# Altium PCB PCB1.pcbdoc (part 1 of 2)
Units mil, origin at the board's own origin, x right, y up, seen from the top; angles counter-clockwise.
Board outline 1771.65 x 1825.33 mil, 2 copper layers (Top Layer, Bottom Layer), stack 62.206 mil thick; 72 components, 46 nets, 229 pads, 305 vias.
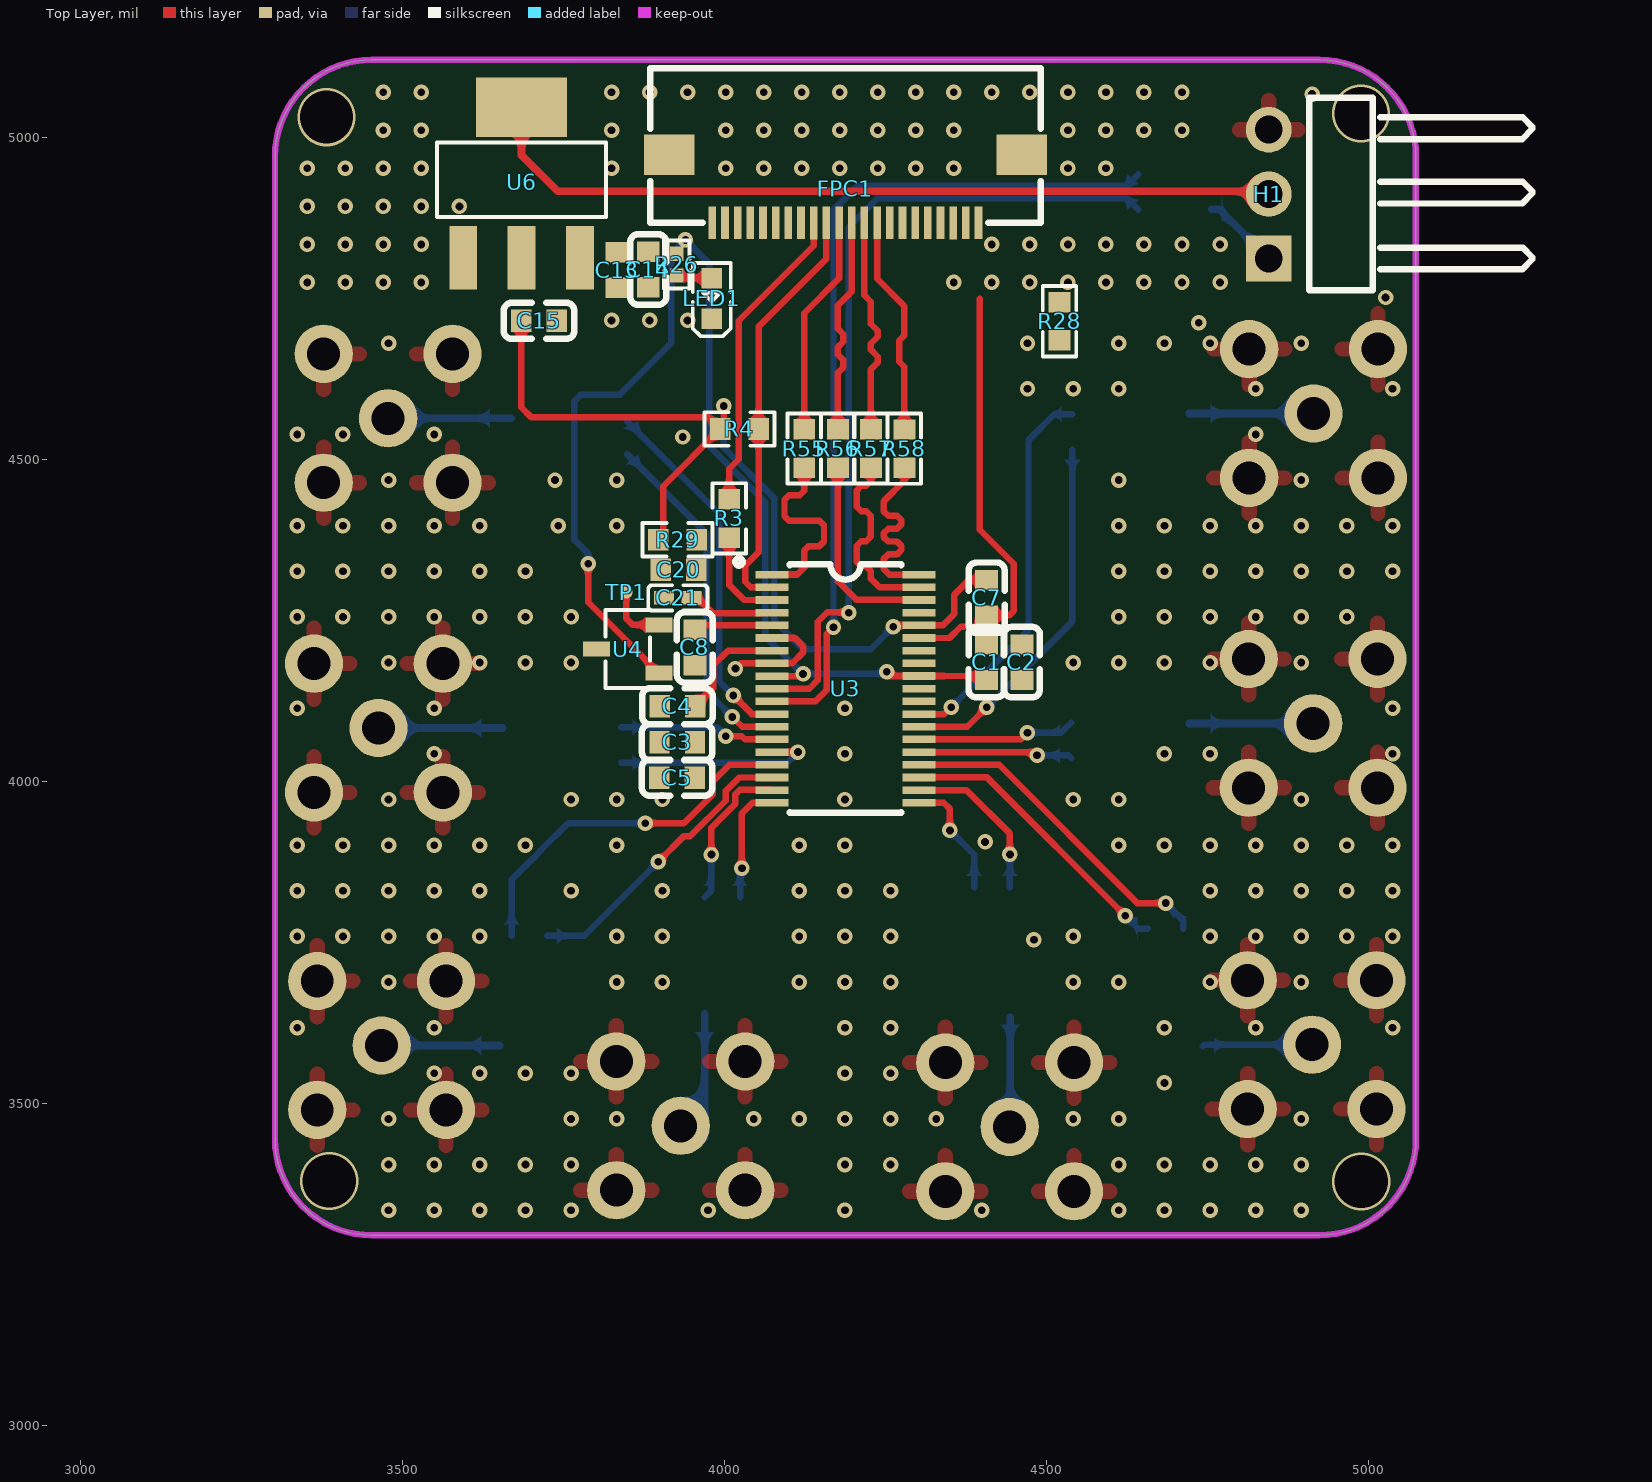
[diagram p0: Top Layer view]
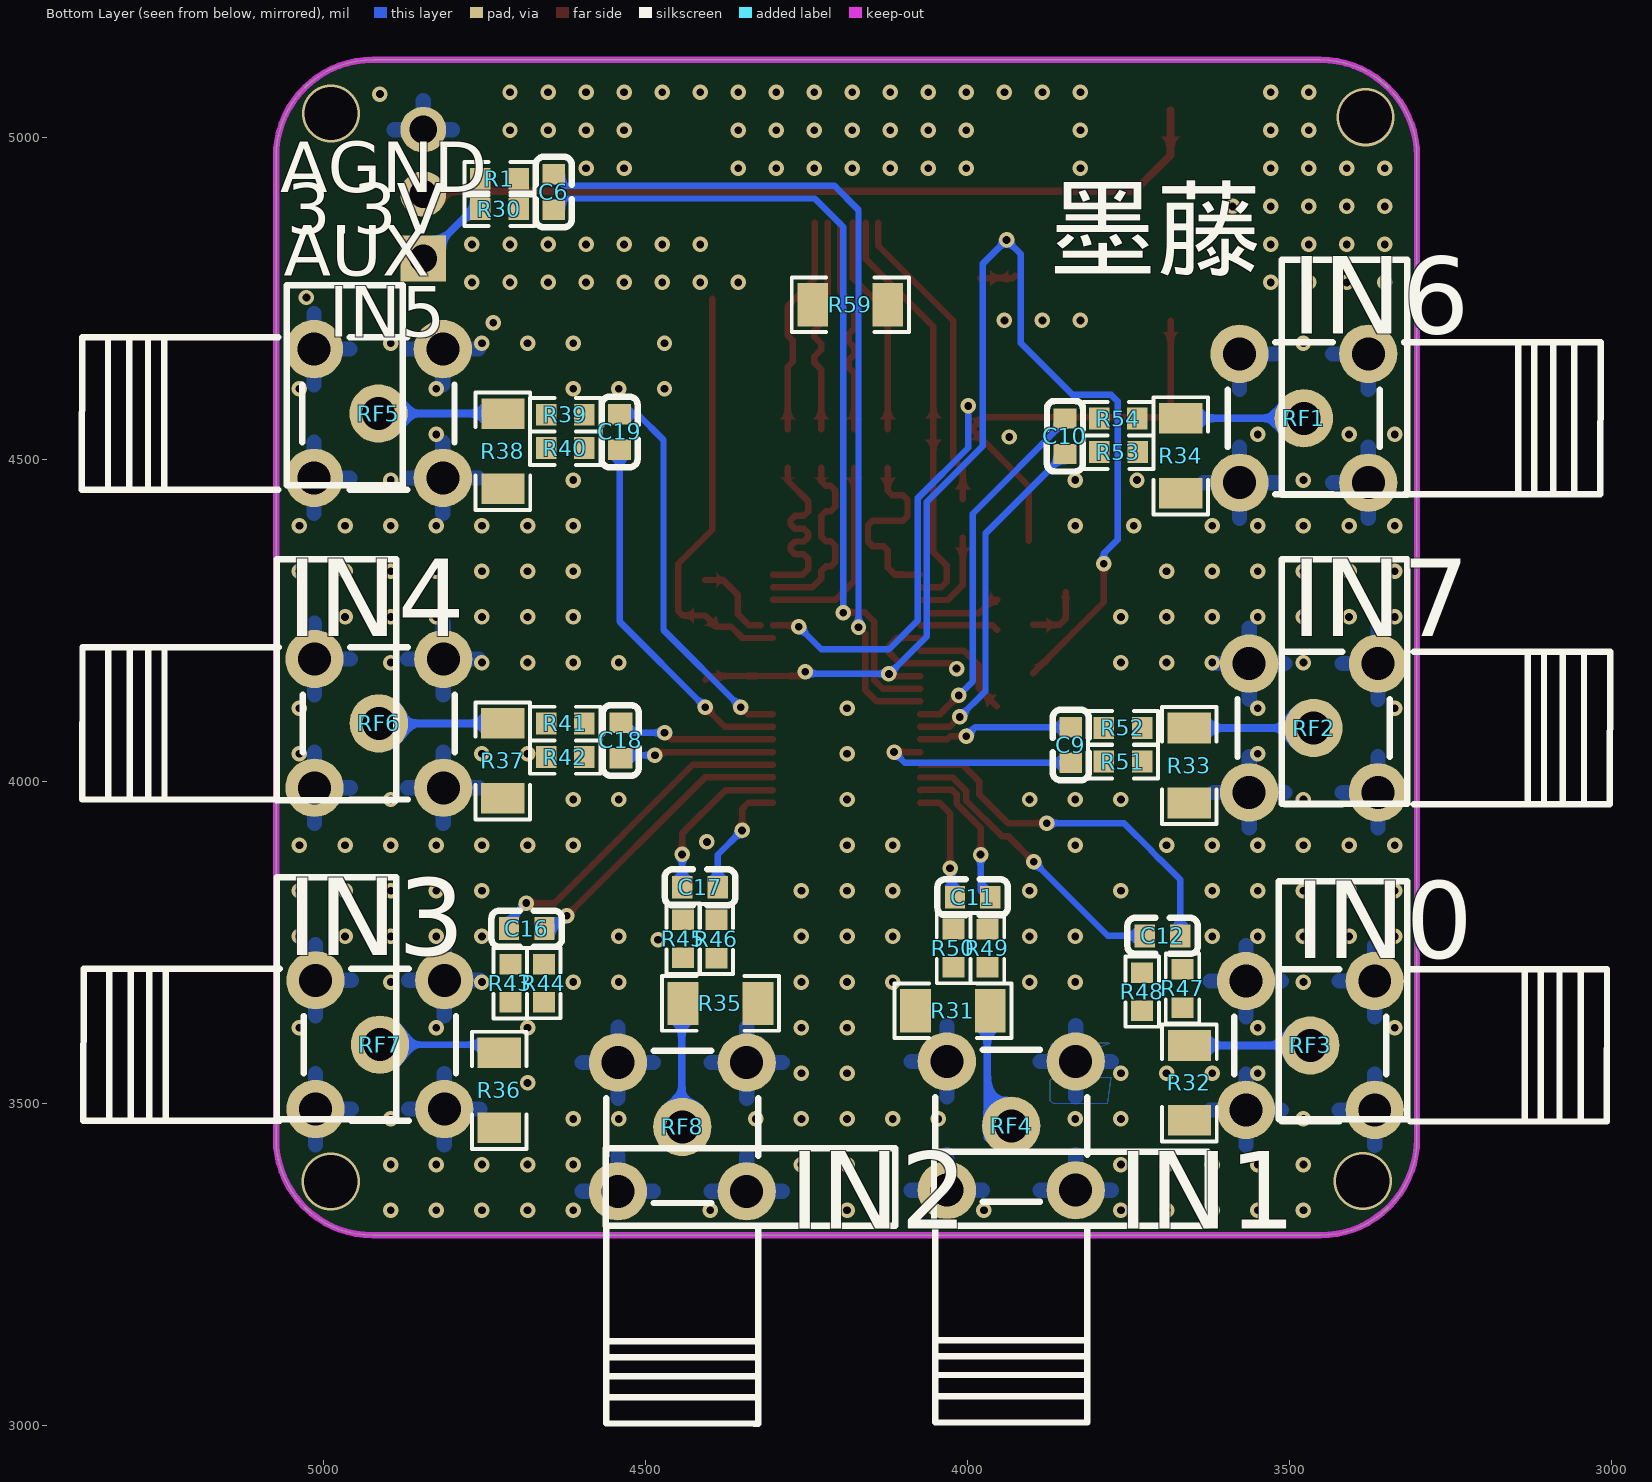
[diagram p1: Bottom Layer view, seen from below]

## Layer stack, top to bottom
Top Solder Mask Layer: solder mask 0.394, Dk 3.3
Top Layer: signal copper 1.379
Dielectric1: surface 59.449, FR4, Dk 4.5
Bottom Layer: signal copper 1.378
Bottom Solder Mask Layer: solder mask 0.394, Dk 3.3

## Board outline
3452.36,3294.69 4924.01,3294.69 ccw(c4924.01,3444.69) 5074.01,3444.69 5074.01,4970.05 ccw(c4924.03,4970.04) 4924.01,5120.02 3452.36,5120.02 ccw(c3452.34,4970.04) 3302.36,4970.05 3302.36,3444.69 ccw(c3452.36,3444.69)

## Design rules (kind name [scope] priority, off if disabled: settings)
BoardOutlineClearance copperThickness1oz [All] p0: genericclearance=10 ignorepadtopadclearanceinfootprint=FALSE except(0: Arc-SplitContinuation Track-SplitContinuation SMDPad-SplitContinuation THPad-SplitContinuation Via-SplitContinuation Fill-SplitContinuation Poly-SplitContinuation Region-SplitContinuation Text-SplitContinuation)
BoardOutlineClearance copperThickness2oz [All] p0: genericclearance=10 ignorepadtopadclearanceinfootprint=FALSE except(0: Arc-SplitContinuation Track-SplitContinuation SMDPad-SplitContinuation THPad-SplitContinuation Via-SplitContinuation Fill-SplitContinuation Poly-SplitContinuation Region-SplitContinuation Text-SplitContinuation)
BoardOutlineClearance Plane_innerPlane [All] p0: genericclearance=10 ignorepadtopadclearanceinfootprint=FALSE except(0: Arc-SplitContinuation Track-SplitContinuation SMDPad-SplitContinuation THPad-SplitContinuation Via-SplitContinuation Fill-SplitContinuation Poly-SplitContinuation Region-SplitContinuation Text-SplitContinuation)
BoardOutlineClearance Copper_copperRegion [All] p0: genericclearance=10 ignorepadtopadclearanceinfootprint=FALSE except(0: Arc-SplitContinuation Track-SplitContinuation SMDPad-SplitContinuation THPad-SplitContinuation Via-SplitContinuation Fill-SplitContinuation Poly-SplitContinuation Region-SplitContinuation Text-SplitContinuation)
BoardOutlineClearance otherClearance [All] p0: genericclearance=10 ignorepadtopadclearanceinfootprint=FALSE except(0: Arc-SplitContinuation Track-SplitContinuation SMDPad-SplitContinuation THPad-SplitContinuation Via-SplitContinuation Fill-SplitContinuation Poly-SplitContinuation Region-SplitContinuation Text-SplitContinuation)
Clearance copperThickness1oz [All] p1: gap=7 ignorepadtopadclearanceinfootprint=FALSE
Clearance copperThickness2oz [All] p1: gap=7 ignorepadtopadclearanceinfootprint=FALSE
Clearance Plane_innerPlane [All] p1: gap=7 ignorepadtopadclearanceinfootprint=FALSE
Clearance Copper_copperRegion [All] p1: gap=7 ignorepadtopadclearanceinfootprint=FALSE
Clearance otherClearance [All] p1: gap=7 ignorepadtopadclearanceinfootprint=FALSE
DiffPairsRouting differentialPair [All] p1: maxuncoupledlength=10 minlimit=6 maxlimit=Infinity mostfreqgap=6 toplayer_minwidth=5 toplayer_prefwidth=10 toplayer_maxwidth=100 bottomlayer_minwidth=5 bottomlayer_prefwidth=10 bottomlayer_maxwidth=100
PasteMaskExpansion pasteMaskExpansion [All] p1: expansion=0
PlaneConnect innerPlane [All] p1: planeconnectstyle=Relief reliefexpansion=20 reliefentries=4 reliefconductorwidth=10 reliefairgap=10
PolygonConnect copperRegion [All] p1: connectstyle=Relief reliefentries=4 reliefconductorwidth=23.622 polygonreliefangle="90 Angle" airgapwidth=10
RoutingVias viaSize [All] p1: viastyle="Through Hole" holewidth=12.0078 minholewidth=11.811 maxholewidth=248.0314 width=12.0078 minwidth=11.811 maxwidth=248.0314
SolderMaskExpansion solderMaskExpansion [All] p1: useseparateexpansions=TRUE expansion=2 expansionbottom=2
Width copperThickness1oz [All] p1: maxlimit=100 minlimit=5 preferedwidth=10
Width copperThickness2oz [All] p1: maxlimit=100 minlimit=8 preferedwidth=10

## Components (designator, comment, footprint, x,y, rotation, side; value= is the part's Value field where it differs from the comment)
C1 "" C0603 4407.22,4184.71 r90 top
C2 "" C0603 4462.22,4184.71 r90 top
C3 "" C0603 3926.83,4060.33 r0 top
C4 "" C0603 3927.19,4116.15 r0 top
C5 "" C0603 3926.8,4005.33 r180 top
C6 "" C0603 4642.72,4914.68 r270 bottom
C7 "" C0603 4407.36,4284.69 r270 top
C8 "" C0603 3954.39,4207.58 r90 top
C9 "" C0603 3840.05,4055.92 r90 bottom
C10 "" C0603 3848.99,4535.49 r90 bottom
C11 "" C0603 3992.36,3819.69 r180 bottom
C12 "" C0603 3697.36,3759.69 r180 bottom
C13 "" C0603 3833.49,4793.58 r90 top
C14 "" C0603 3881.86,4794.37 r90 top
C15 "" C0603 3712.36,4714.69 r0 top
C16 "" C0603 4684.84,3770.9 r180 bottom
C17 "" C0603 4415.55,3835.13 r180 bottom
C18 "" C0603 4538.61,4063.17 r270 bottom
C19 "" C0603 4540.63,4542.11 r270 bottom
C20 "" C0603 3928.98,4328.3 r180 top
C21 "" C0402 3927.97,4284.52 r180 top
FPC1 "" FPC-SMD_P0.5-22P_FGS-XJ-H2.0 4188.19,4919.69 r0 top
H1 "" HDR-TH_3P-P2.54-H-M-W10.4 4845.4,4911.52 r90 top
LED1 "" LED0603-RD 3980.72,4749.54 r90 top
R1 "" R0603 4727.09,4935.36 r180 bottom
R3 "" R0603 4007.66,4407.87 r270 top
R4 "" R0603 4023.54,4546.77 r180 top
R26 "" R0402 3926.22,4802.07 r90 top
R28 "" R0603 4520.58,4714.08 r270 top
R29 "" R0603 3927.36,4374.69 r180 top
R30 "" R0603 4727.09,4888.06 r180 bottom
R31 "" R1206 4022.94,3643.34 r180 bottom
R32 "" R1206 3655.84,3531.3 r90 bottom
R33 "" R1206 3655.97,4024.17 r90 bottom
R34 "" R1206 3669.23,4505.1 r90 bottom
R35 "" R1206 4383.9,3654.9 r0 bottom
R36 "" R1206 4727.36,3519.69 r90 bottom
R37 "" R1206 4721.99,4031.31 r90 bottom
R38 "" R1206 4721.81,4512.16 r270 bottom
R39 "" R0603 4624.95,4568.91 r0 bottom
R40 "" R0603 4624.93,4517.02 r0 bottom
R41 "" R0603 4625,4089.5 r0 bottom
R42 "" R0603 4624.96,4037.31 r0 bottom
R43 "" R0603 4710.27,3686.16 r270 bottom
R44 "" R0603 4658.24,3686.19 r270 bottom
R45 "" R0603 4441.96,3755.31 r270 bottom
R46 "" R0603 4390.34,3754.71 r270 bottom
R47 "" R0603 3666.46,3678.02 r90 bottom
R48 "" R0603 3729.16,3673.02 r90 bottom
R49 "" R0603 3969.38,3740.61 r90 bottom
R50 "" R0603 4022.08,3740.61 r90 bottom
R51 "" R0603 3758.88,4030.32 r0 bottom
R52 "" R0603 3758.88,4082.62 r0 bottom
R53 "" R0603 3765.94,4510.75 r0 bottom
R54 "" R0603 3766.09,4562.77 r0 bottom
R55 "" R0603 4124.2,4516.4 r90 top
R56 "" R0603 4176.5,4516.4 r90 top
R57 "" R0603 4227.53,4516.4 r90 top
R58 "" R0603 4279.58,4516.33 r90 top
R59 "" R1206 4182.36,4739.69 r180 bottom
RF1 "" ANT-TH_KH-SMA-K513-G 3477.99,4563.39 r0 bottom
RF2 "" ANT-TH_KH-SMA-K513-G 3462.99,4082.44 r0 bottom
RF3 "" ANT-TH_KH-SMA-K513-G 3467.99,3589.49 r0 bottom
RF4 "" ANT-TH_KH-SMA-K513-G 3932.36,3464.69 r90 bottom
RF5 "" ANT-TH_KH-SMA-K513-G 4915.03,4570.78 r180 bottom
RF6 "" ANT-TH_KH-SMA-K513-G 4914.35,4089.56 r180 bottom
RF7 "" ANT-TH_KH-SMA-K513-G 4912.74,3590.69 r180 bottom
RF8 "" ANT-TH_KH-SMA-K513-G 4443.16,3462.99 r90 bottom
TP1 "" Test-Point-0.5mm 3847.89,4293.39 r0 top
U3 "" TSSOP-38_L9.7-W4.4-P0.50-LS6.4-BL 4188.19,4143.47 r270 top
U4 "" SOT-23-3_L2.9-W1.6-P1.90-LS2.8-BR 3849.99,4205.09 r0 top
U6 "" SOT-223-3_L6.5-W3.4-P2.30-LS7.0-BR 3685.14,4929.68 r270 top

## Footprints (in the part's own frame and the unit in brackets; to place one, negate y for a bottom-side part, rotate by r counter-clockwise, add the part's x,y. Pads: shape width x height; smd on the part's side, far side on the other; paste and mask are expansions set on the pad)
ANT-TH_KH-SMA-K513-G [mm]
  round 2.3 hole 1.3: 1(-2.54,-2.54) 2(-2.54,2.54) 3(2.54,2.54) 4(2.54,-2.54) 5(0,0)
  silkscreen extent -11.7,-3 3,3
C0402 [mm]
  rect 0.79x0.54 smd: 1(-0.545,0) 2(0.545,0)
  silkscreen extent -1.17,-0.5 1.17,0.5
C0603 [mm]
  rect 0.8x0.9 smd: 1(-0.7,0) 2(0.7,0)
  silkscreen extent -1.39,-0.71 1.39,0.71
FPC-SMD_P0.5-22P_FGS-XJ-H2.0 [mm]
  rect 0.3x1.3 smd: 1(-5.252,-1.338) 2(-4.752,-1.338) 3(-4.252,-1.338) 4(-3.752,-1.338) 5(-3.252,-1.338) 6(-2.752,-1.338) 7(-2.252,-1.338) 8(-1.752,-1.338) 9(-1.25,-1.339) 10(-0.752,-1.338) 11(-0.252,-1.338) 12(0.248,-1.338) 13(0.748,-1.338) 14(1.248,-1.338) 15(1.748,-1.338) 16(2.248,-1.338) 17(2.748,-1.338) 18(3.248,-1.338) 19(3.748,-1.338) 20(4.25,-1.339) 21(4.748,-1.338) 22(5.248,-1.338)
  rect 2x1.6 smd: 23(6.95,1.339) 24(-6.95,1.339)
  silkscreen extent -7.7,-1.34 7.7,4.76
HDR-TH_3P-P2.54-H-M-W10.4 [mm]
  rect 1.8x1.8 hole 1.1: 1(-2.54,0)
  round 1.8 hole 1.1: 2(0,0) 3(2.54,0)
  silkscreen extent -3.8,-10.4 3.8,-1.6
LED0603-RD [mm]
  rect 0.8x0.8 smd: 1(-0.799,0) 2(0.799,0)
  silkscreen extent -1.49,-0.75 1.39,0.76
R0402 [mm]
  rect 0.566x0.54 smd: 1(-0.433,0) 2(0.433,0)
  silkscreen extent -0.94,-0.5 0.94,0.5
R0603 [mil]
  rect 31.75x34.02 smd: 1(-29.66,0) 2(29.66,0)
  silkscreen extent -55,-26 55,26
R1206 [mil]
  rect 47.54x66.97 smd: 1(-58.22,0) 2(58.22,0)
  silkscreen extent -91,-42 91,42
SOT-23-3_L2.9-W1.6-P1.90-LS2.8-BR [mm]
  rect 1.07x0.6 smd: 1(1.235,-0.95) 2(1.235,0.95) 3(-1.235,0)
  silkscreen extent -0.88,-1.54 0.88,1.54
SOT-223-3_L6.5-W3.4-P2.30-LS7.0-BR [mm]
  rect 2.5x1.1 smd: 1(2.97,-2.3) 2(2.97,0) 3(2.97,2.3)
  rect 2.34x3.6 smd: 4(-2.97,0)
  silkscreen extent -1.57,-3.33 1.37,3.33
Test-Point-0.5mm [mm]
  round 0.5 smd: 1(0,0)
TSSOP-38_L9.7-W4.4-P0.50-LS6.4-BL [mm]
  rect 0.3x1.3 smd: 1(-4.501,-2.899) 2(-3.999,-2.901) 3(-3.498,-2.901) 4(-2.999,-2.901) 5(-2.499,-2.901) 6(-1.999,-2.901) 7(-1.499,-2.901) 8(-0.999,-2.901) 9(-0.499,-2.901) 10(0.001,-2.901) 11(0.501,-2.901) 12(1.001,-2.901) 13(1.501,-2.901) 14(2.001,-2.901) 15(2.501,-2.901) 16(3.001,-2.901) 17(3.501,-2.901) 18(4.001,-2.901) 19(4.501,-2.901) 20(4.5,2.899) 21(4.001,2.9) 22(3.501,2.899) 23(3.002,2.899) 24(2.499,2.901) 25(2,2.9) 26(1.5,2.9) 27(1,2.9) 28(0.5,2.9) 29(0,2.9) 30(-0.5,2.9) 31(-1,2.9) 32(-1.5,2.9) 33(-2,2.9) 34(-2.5,2.9) 35(-3,2.9) 36(-3.5,2.9) 37(-4,2.9) 38(-4.5,2.9)
  silkscreen extent -5.14,-4.34 4.9,2.2

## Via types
v1: diameter 24.02, hole 12.01, Top Layer to Bottom Layer, 301 vias
v2: diameter 90.55, hole 82.68, Top Layer to Bottom Layer, 4 vias

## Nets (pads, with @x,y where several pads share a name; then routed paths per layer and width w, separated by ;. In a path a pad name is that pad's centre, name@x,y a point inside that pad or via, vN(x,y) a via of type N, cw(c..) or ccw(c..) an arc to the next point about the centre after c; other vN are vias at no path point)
3.3V: C7.1 C15.1 H1.2 R4.2 R29.2 U3.34 U6.2 U6.4 | length 2716.9
  Top Layer w10: C15.1@3684.8,4714.69 3684.8,4580.67 3700.78,4564.69 3975.96,4564.69 R4.2@3993.88,4546.77 ; R29.2@3905.16,4373.36 3905.16,4458.05 R4.2@3993.88,4546.77 ; v1(3999.37,4582.53) 3999.37,4552.26 R4.2@3993.88,4546.77 ; v1(4262.36,4239.69) 4264.56,4241.89 U3.34@4302.35,4241.89 ; U3.34@4321.64,4242.02 4339.69,4242.02 4357.36,4259.69 4357.36,4289.69 4379.92,4312.25 C7.1@4407.36,4312.25
  Top Layer w12: U6.4@3685.14,5041.6 3685.14,4971.92 3741.32,4915.73 4841.18,4915.73 H1.2@4845.4,4911.52
  Bottom Layer w10: v1(3999.37,4582.53) 3999.37,4517.68 4077.36,4439.69 4077.36,4249.69 4122.36,4204.69 4227.36,4204.69 v1(4262.36,4239.69)
5V_USB: C1.1 C2.1 C13.2 C14.2 FPC1.1 FPC1.2 FPC1.3 FPC1.4 FPC1.5 FPC1.6 FPC1.7 FPC1.8 R26.2 U3.9 U3.30 U4.1 U6.3 | length 1923.4
  Top Layer w10: v1(3788.61,4337.69) 3788.61,4277.69 U4.1@3898.61,4167.69 ; U3.9@4073.97,4163.11 4119.05,4163.11 v1(4122.36,4166.42) ; v1(4252.36,4169.69) 4258.91,4163.15 U3.30@4302.35,4163.15 4401.22,4163.15 C1.1@4407.22,4157.15
  Bottom Layer w10: v1(3788.61,4337.69) 3788.61,4353.44 3767.36,4374.69 3767.36,4589.69 3777.36,4599.69 3837.36,4599.69 3917.36,4679.69 3917.36,4817.96 v1(3939.71,4840.31) 3976.38,4803.64 3976.38,4520.85 4063.35,4433.89 4063.35,4224.87 v1@4121.34,4166.87 ; v1(4122.36,4166.42) 4249.09,4166.42 v1(4252.36,4169.69)
$1N881: C3.2 C4.2 C5.1 U3.7 | length 175.6
  Top Layer w10: C4.2@3954.75,4116.15 3983.09,4144.49 3983.09,4179.69 4005.88,4202.48 U3.7@4073.97,4202.48
$1N1310: R3.2 U3.3 | length 149.7
  Top Layer w10: R3.2@4007.66,4378.21 4007.66,4304.39 4030.86,4281.2 U3.3@4073.97,4281.2
$1N2306: C20.1 C21.1 R29.1 U3.4 | length 112.3
  Top Layer w10: C21.1@3954.21,4281.44 3962.38,4281.44 3983.07,4260.75 U3.4@4057.98,4260.75
$1N2496: C10.2 R54.2 U3.12 | length 570.3
  Top Layer w10: v1(4014.09,4132.97) 4043,4104.06 U3.12@4073.97,4104.06
  Bottom Layer w10: C10.2@3848.99,4563.05 3848.99,4558.65 3992.36,4415.28 3992.36,4154.69 v1(4014.09,4132.97)
$1N2502: C10.1 R53.2 U3.13 | length 543.9
  Top Layer w10: v1(4012.36,4099.69) 4027.69,4084.37 U3.13@4073.97,4084.37
  Bottom Layer w10: C10.1@3848.99,4507.93 3972.36,4384.56 3972.36,4139.69 v1(4012.36,4099.69)
$1N2508: C9.2 R52.2 U3.14 | length 241.7
  Top Layer w10: v1(4002.36,4069.69) 4027.36,4069.69 4032.36,4064.69 U3.14@4073.97,4064.69
  Bottom Layer w10: C9.2@3840.05,4083.48 3988.57,4083.48 v1(4002.36,4069.69)
$1N2515: C9.1 R51.2 U3.15 | length 324.7
  Top Layer w10: U3.15@4073.97,4045 4117.06,4045 v1@4117.36,4044.69
  Bottom Layer w10: C9.1@3840.05,4028.36 4097.66,4028.36 v1(4114.36,4045.06)
$1N2525: C12.2 R47.2 U3.16 | length 577.5
  Top Layer w10: v1(3877.36,3934.69) 3937.36,3934.69 3982.36,3979.69 3982.36,3999.69 4007.99,4025.32 U3.16@4073.97,4025.32
  Bottom Layer w10: C12.2@3669.8,3759.69 3669.8,3847.13 3700.24,3877.57 3700.82,3877.57 3714.29,3891.03 3714.29,3891.62 3757.36,3934.69 v1(3877.36,3934.69)
$1N2534: C11.2 R49.2 U3.18 | length 239.9
  Top Layer w10: v1(3980.1,3885.86) 3980.1,3927.43 4017.36,3964.69 4017.36,3979.69 4024.43,3986.76 4073.16,3986.76 U3.18@4073.97,3985.95
  Bottom Layer w10: C11.2@3969.49,3819.48 3980.1,3830.09 v1(3980.1,3885.86)
$1N2541: C12.1 R48.2 U3.17 | length 459.7
  Top Layer w10: v1(3897.36,3874.69) 3937.36,3914.69 3947.36,3914.69 4002.36,3969.69 4002.36,3984.69 4023.3,4005.63 U3.17@4073.97,4005.63
  Bottom Layer w10: C12.1@3724.92,3759.69 3782.36,3759.69 v1(3897.36,3874.69)
$1N2549: C11.1 R50.2 U3.19 | length 184.8
  Top Layer w10: v1(4027.36,3864.69) 4027.36,3949.69 4043.93,3966.26 U3.19@4073.97,3966.26
  Bottom Layer w10: C11.1@4024.61,3819.48 4024.61,3861.94 v1(4027.36,3864.69)
$1N3102: C19.1 R39.1 U3.27 | length 603.9
  Top Layer w10: U3.27@4302.35,4104.1 4341.77,4104.1 v1(4352.36,4114.69)
  Bottom Layer w10: v1(4352.36,4114.69) 4472.36,4234.69 4472.36,4529.69 4512.34,4569.67 C19.1@4540.63,4569.67
$1N3111: C19.2 R40.1 U3.26 | length 572.6
  Top Layer w10: U3.26@4302.35,4084.41 4377.08,4084.41 v1(4407.36,4114.69)
  Bottom Layer w10: v1(4407.36,4114.69) 4540.63,4247.96 C19.2@4540.63,4514.55
$1N3136: C16.1 R43.1 U3.23 | length 523
  Top Layer w10: U3.23@4302.33,4025.28 4426.78,4025.28 4641.4,3810.65 v1(4685.5,3810.65)
  Bottom Layer w10: v1(4685.5,3810.65) 4712.4,3783.75 C16.1@4712.4,3770.9
$1N3142: C16.2 R44.1 U3.22 | length 452.2
  Top Layer w10: U3.22@4302.33,4005.66 4407.97,4005.66 v1(4622.74,3790.89)
  Bottom Layer w10: v1(4622.74,3790.89) 4642.72,3770.9 C16.2@4657.28,3770.9
$1N3148: C17.1 R45.1 U3.21 | length 252.7
  Top Layer w10: U3.21@4302.36,3985.94 4376.12,3985.94 4443.53,3918.52 v1(4443.53,3886.07)
  Bottom Layer w10: C17.1@4443.11,3835.13 4443.53,3835.56 v1(4443.53,3886.07)
$1N3155: C17.2 R46.1 U3.20 | length 189.1
  Top Layer w10: U3.20@4302.33,3966.29 4340.77,3966.29 4350.41,3956.64 v1(4350.41,3923.33)
  Bottom Layer w10: v1(4350.41,3923.33) 4387.99,3885.75 C17.2@4387.99,3835.13
$1N3547: R34.2 R54.1 RF1.5 | length 191.3
  Bottom Layer w12: RF1.5@3477.99,4563.39 3669.15,4563.39 R34.2@3669.23,4563.32
$1N3571: R33.2 R52.1 RF2.5 | length 192.9
  Bottom Layer w12: RF2.5@3462.99,4082.44 R33.2@3655.92,4082.44
$1N3593: R32.2 R47.1 RF3.5 | length 192.8
  Bottom Layer w12: RF3.5@3458.01,3589.52 R32.2@3650.84,3589.52
$1N3616: R31.2 R49.1 RF4.5 | length 191.9
  Bottom Layer w12: RF4.5@3969.64,3446.49 3969.64,3638.26 R31.2@3969.72,3638.34
$1N11847: C6.1 R1.2 U3.11 | length 1338.3
  Top Layer w10: U3.11@4073.97,4123.74 4141.41,4123.74 4159.37,4141.7 4159.37,4228.77 v1(4169.59,4238.99)
  Bottom Layer w10: v1(4169.59,4238.99) 4169.59,4886.92 4207.36,4924.69 4625.17,4924.69 C6.1@4642.72,4942.24
$1N11929: C6.2 R30.2 U3.10 | length 1295.6
  Top Layer w10: U3.10@4073.97,4143.43 4131.88,4143.43 4145.35,4156.89 4145.35,4247.27 4160.06,4261.98 4192.56,4261.98 v1(4193.1,4261.43)
  Bottom Layer w10: v1(4193.1,4261.43) 4193.1,4860.43 4237.36,4904.69 4625.14,4904.69 C6.2@4642.72,4887.12
$1N12022: LED1.2 R26.1 | length 56.2
  Top Layer w10: R26.1@3926.22,4785.03 3930.24,4781.01 LED1.2@3980.71,4781.01
$1N16896: R38.1 R39.2 RF5.5 | length 193.4
  Bottom Layer w12: R38.1@4721.81,4570.38 4722.21,4570.78 RF5.5@4915.03,4570.78
$1N16947: R37.2 R41.2 RF6.5 | length 192.3
  Bottom Layer w12: R37.2@4721.99,4089.53 RF6.5@4914.31,4089.53
$1N17152: R36.2 R43.2 RF7.5 | length 170.7
  Bottom Layer w10: R36.2@4742.98,3588.3 4745.37,3590.69 RF7.5@4912.74,3590.69
$1N17239: C18.2 R42.1 U3.24 | length 240.1
  Top Layer w10: U3.24@4302.4,4045.09 4480.68,4045.09 v1(4485.67,4040.09)
  Bottom Layer w10: v1(4485.67,4040.09) 4534.12,4040.09 C18.2@4538.61,4035.61
$1N17244: C18.1 R41.1 U3.25 | length 247
  Top Layer w10: U3.25@4302.35,4064.73 4460.31,4064.73 v1(4470.67,4075.09)
  Bottom Layer w10: v1(4470.67,4075.09) 4522.97,4075.09 C18.1@4538.61,4090.73
$1N17369: C8.2 TP1.1 U3.5 U4.2 | length 218.1
  Top Layer w10: TP1.1@3847.89,4293.39 3847.89,4252.49 3857.89,4242.49 U4.2@3898.61,4242.49 ; C8.2@3954.39,4235.14 3961.09,4241.85 U3.5@4073.97,4241.85
$1N20017: R35.2 R45.2 RF8.5 | length 178.6
  Bottom Layer w12: RF8.5@4423.16,3462.99 4444.19,3484.02 R35.2@4444.19,3632.84
AGND: C1.2 C2.2 C3.1 C4.1 C5.2 C8.1 C20.2 C21.2 H1.3 R1.1 R28.2 R31.1 R32.1 R33.1 R34.1 R35.1 R36.1 R37.1 R38.2 R40.2 R42.2 R44.2 R46.2 R48.1 R50.1 R51.1 R53.1 RF1.1 RF1.2 RF1.3 RF1.4 RF2.1 RF2.2 RF2.3 RF2.4 RF3.1 RF3.2 RF3.3 RF3.4 RF4.1 RF4.2 RF4.3 RF4.4 RF5.1 RF5.2 RF5.3 RF5.4 RF6.1 RF6.2 RF6.3 RF6.4 RF7.1 RF7.2 RF7.3 RF7.4 RF8.1 RF8.2 RF8.3 RF8.4 U3.6 U3.8 U3.28 U3.29 U3.31 U3.32 U4.3 | length 178.9
  Top Layer w10: v1(4017.36,4174.69) 4025.47,4182.8 U3.8@4073.97,4182.8 4105.47,4182.8 4122.36,4199.69 4122.36,4209.69 4109.89,4222.17 U3.6@4073.97,4222.17
  other v1: 3478.7,3333.63 3549.57,3333.63 3620.43,3333.63 3691.3,3333.63 3762.16,3333.63 3974.76,3333.63 4187.36,3333.63 4399.96,3333.63 4612.56,3333.63 4683.42,3333.63 4754.29,3333.63 4825.16,3333.63 4896.02,3333.63 3478.7,3404.5 3549.57,3404.5 3620.43,3404.5 3691.3,3404.5 3762.16,3404.5 4187.36,3404.5 4258.23,3404.5 4612.56,3404.5 4683.42,3404.5 4754.29,3404.5 4825.16,3404.5 4896.02,3404.5 3478.7,3475.36 3762.16,3475.36 3833.03,3475.36 4045.63,3475.36 4116.49,3475.36 4187.36,3475.36 4258.23,3475.36 4329.09,3475.36 4541.69,3475.36 4612.56,3475.36 4896.02,3475.36 4683.42,3531.23 3549.57,3546.23 3620.43,3546.23 3691.3,3546.23 3762.16,3546.23 4187.36,3546.23 4258.23,3546.23 3336.97,3617.09 3549.57,3617.09 4187.36,3617.09 4258.23,3617.09 4683.42,3617.09 4825.16,3617.09 5037.75,3617.09 3478.7,3687.96 3833.03,3687.96 3903.9,3687.96 4116.49,3687.96 4187.36,3687.96 4258.23,3687.96 4541.69,3687.96 4612.56,3687.96 4754.29,3687.96 4896.02,3687.96 4480.82,3753.83 3336.97,3758.83 3407.83,3758.83 3478.7,3758.83 3549.57,3758.83 3620.43,3758.83 3833.03,3758.83 3903.9,3758.83 4116.49,3758.83 4187.36,3758.83 4258.23,3758.83 4541.69,3758.83 4754.29,3758.83 4825.16,3758.83 4896.02,3758.83 4966.89,3758.83 5037.75,3758.83 3336.97,3829.69 3407.83,3829.69 3478.7,3829.69 3549.57,3829.69 3620.43,3829.69 3762.16,3829.69 3903.9,3829.69 4116.49,3829.69 4187.36,3829.69 4258.23,3829.69 4754.29,3829.69 4825.16,3829.69 4896.02,3829.69 4966.89,3829.69 5037.75,3829.69 3336.97,3900.56 3407.83,3900.56 3478.7,3900.56 3549.57,3900.56 3620.43,3900.56 3691.3,3900.56 3833.03,3900.56 4116.49,3900.56 4187.36,3900.56 4612.56,3900.56 4683.42,3900.56 4754.29,3900.56 4825.16,3900.56 4896.02,3900.56 4966.89,3900.56 5037.75,3900.56 4404.96,3905.56 3478.7,3971.42 3762.16,3971.42 3833.03,3971.42 3903.9,3971.42 4187.36,3971.42 4541.69,3971.42 4612.56,3971.42 4896.02,3971.42 3549.57,4042.29 4187.36,4042.29 4683.42,4042.29 4754.29,4042.29 5037.75,4042.29 3336.97,4113.16 3549.57,4113.16 4187.36,4113.16 5037.75,4113.16 3478.7,4184.02 3620.43,4184.02 3691.3,4184.02 3762.16,4184.02 4541.69,4184.02 4612.56,4184.02 4683.42,4184.02 4754.29,4184.02 4896.02,4184.02 3336.97,4254.89 3407.83,4254.89 3478.7,4254.89 3549.57,4254.89 3620.43,4254.89 3691.3,4254.89 3762.16,4254.89 4612.56,4254.89 4683.42,4254.89 4754.29,4254.89 4825.16,4254.89 4896.02,4254.89 4966.89,4254.89 3336.97,4325.75 3407.83,4325.75 3478.7,4325.75 3549.57,4325.75 3620.43,4325.75 3691.3,4325.75 4612.56,4325.75 4683.42,4325.75 4754.29,4325.75 4825.16,4325.75 4896.02,4325.75 4966.89,4325.75 5037.75,4325.75 3336.97,4396.62 3407.83,4396.62 3478.7,4396.62 3549.57,4396.62 3620.43,4396.62 3742.16,4396.62 3833.03,4396.62 4612.56,4396.62 4683.42,4396.62 4754.29,4396.62 4825.16,4396.62 4896.02,4396.62 4966.89,4396.62 5037.75,4396.62 3478.7,4467.49 3737.16,4467.49 3833.03,4467.49 4612.56,4467.49 4896.02,4467.49 3935.49,4534.31 3336.97,4538.35 3407.83,4538.35 3549.57,4538.35 4825.16,4538.35 4470.82,4609.22 4541.69,4609.22 4612.56,4609.22 4825.16,4609.22 5037.75,4609.22 3478.7,4680.09 4470.82,4680.09 4612.56,4680.09 4683.42,4680.09 4754.29,4680.09 4896.02,4680.09 4736.89,4711.82 5026.89,4750.95 4912.75,5066.82
  other v2: 4989.1,3378.39 3386.66,3378.99 4988.84,5036.6
AUX: H1.1 R30.1 | length 120.3
  Bottom Layer w12: R30.1@4756.75,4888.06 4768.86,4888.06 H1.1@4845.4,4811.52
CS: R58.1 U3.38 | length 307.4
  Top Layer w10: R58.1@4279.58,4486.67 4279.58,4466.29 4247.36,4434.07 4247.36,4419.08 4254.43,4412.01 4268.16,4412.01 4275.23,4404.94 4275.23,4399.08 4268.16,4392.01 4254.43,4392.01 4247.36,4384.94 4247.36,4379.08 4254.43,4372.01 4268.16,4372.01 4275.23,4364.94 4275.23,4359.08 4268.16,4352.01 4254.43,4352.01 4247.36,4344.94 4247.36,4329.69 4256.43,4320.63 U3.38@4302.35,4320.63
DAISY: FPC1.9 R3.1 | length 483.8
  Top Layer w10: R3.1@4007.66,4437.53 4007.66,4484.99 4022.36,4499.69 4022.36,4714.69 4138.98,4831.31 FPC1.9@4138.98,4866.96
GND: C7.2 C13.1 C14.1 C15.2 FPC1.15 FPC1.16 FPC1.17 FPC1.18 FPC1.19 FPC1.20 FPC1.21 FPC1.22 FPC1.23 FPC1.24 LED1.1 R28.1 R59.1 R59.2 U3.33 U6.1 | length 671.1
  Top Layer w10: U3.33@4302.35,4222.21 4349.88,4222.21 4367.36,4239.69 4389.92,4239.69 C7.2@4407.36,4257.13 4442.36,4257.13 4449.43,4264.2 4449.43,4337.62 4396.73,4390.32 4396.73,4748.98
  other v1: 3824.92,4715.24 3883.97,4715.24 3943.03,4715.24 3352.48,4774.3 3411.53,4774.3 3470.59,4774.3 3529.64,4774.3 4356.42,4774.3 4415.47,4774.3 4474.53,4774.3 4533.58,4774.3 4592.64,4774.3 4651.69,4774.3 4710.75,4774.3 4769.8,4774.3 3352.48,4833.35 3411.53,4833.35 3470.59,4833.35 3529.64,4833.35 4415.47,4833.35 4474.53,4833.35 4533.58,4833.35 4592.64,4833.35 4651.69,4833.35 4710.75,4833.35 4769.8,4833.35 3352.48,4892.41 3411.53,4892.41 3470.59,4892.41 3529.64,4892.41 3588.7,4892.41 3352.48,4951.46 3411.53,4951.46 3470.59,4951.46 3529.64,4951.46 3824.92,4951.46 4002.09,4951.46 4061.14,4951.46 4120.2,4951.46 4179.25,4951.46 4238.31,4951.46 4297.36,4951.46 4356.42,4951.46 4533.58,4951.46 4592.64,4951.46 3470.59,5010.52 3529.64,5010.52 3824.92,5010.52 4002.09,5010.52 4061.14,5010.52 4120.2,5010.52 4179.25,5010.52 4238.31,5010.52 4297.36,5010.52 4356.42,5010.52 4533.58,5010.52 4592.64,5010.52 4651.69,5010.52 4710.75,5010.52 3470.59,5069.57 3529.64,5069.57 3824.92,5069.57 3883.97,5069.57 3943.03,5069.57 4002.09,5069.57 4061.14,5069.57 4120.2,5069.57 4179.25,5069.57 4238.31,5069.57 4297.36,5069.57 4356.42,5069.57 4415.47,5069.57 4474.53,5069.57 4533.58,5069.57 4592.64,5069.57 4651.69,5069.57 4710.75,5069.57
  other v2: 3382.29,5031.05
RST: FPC1.10 R4.1 U3.2 | length 654.9
  Top Layer w10: U3.2@4073.97,4300.91 4041.15,4300.91 4032.36,4309.69 4032.36,4334.69 4053.2,4355.53 R4.1@4053.2,4546.77 4053.2,4705.53 4158.58,4810.91 FPC1.10@4158.58,4867.02
SCLK: R57.1 U3.37 | length 307.6
  Top Layer w10: R57.1@4227.53,4486.74 4227.53,4465.53 4220.46,4458.45 4212.59,4458.45 4205.52,4451.38 4205.52,4426.16 4212.59,4419.08 4220.46,4419.08 4227.53,4412.01 4227.53,4379.71 4220.46,4372.64 4212.59,4372.64 4205.52,4365.57 4205.52,4340.34 4212.59,4333.27 4220.46,4333.27 4227.53,4326.2 4227.53,4314.52 4241.11,4300.95 U3.37@4302.35,4300.95
SDI: R55.1 U3.1 | length 307.7
  Top Layer w10: U3.1@4074.07,4320.69 4113.36,4320.69 4124.2,4331.53 4124.2,4357.94 4131.27,4365.01 4147.81,4365.01 4154.89,4372.08 4154.89,4397.31 4147.81,4404.38 4100.59,4404.38 4093.52,4411.45 4093.52,4436.68 4100.59,4443.75 4117.13,4443.75 4124.2,4450.82 R55.1@4124.2,4486.74
SDO: R56.1 U3.36 | length 314.2
  Top Layer w10: R56.1@4176.5,4486.74 4176.5,4310.55 4205.8,4281.26 U3.36@4302.35,4281.26
SPI1_CS: FPC1.14 R58.2 | length 345.1
  Top Layer w10: FPC1.14@4237.32,4867.02 4237.32,4779.86 4279.58,4737.59 4279.58,4691.91 4271.71,4684.04 4271.71,4651.26 4279.58,4643.39 R58.2@4279.58,4545.99
SPI1_MISO: FPC1.12 R56.2 | length 343.5
  Top Layer w10: R56.2@4176.5,4546.06 4176.5,4634.01 4184.74,4642.25 4184.74,4654.01 4176.5,4662.25 4176.5,4674.01 4184.74,4682.25 4184.74,4694.01 4176.5,4702.25 4176.5,4738.83 4197.95,4760.28 FPC1.12@4197.95,4867.02
SPI1_MOSI: FPC1.11 R55.2 | length 343.4
  Top Layer w10: R55.2@4124.2,4546.06 4124.2,4726.53 4178.27,4780.6 FPC1.11@4178.27,4867.02
SPI1_SCK: FPC1.13 R57.2 | length 343.3
  Top Layer w10: FPC1.13@4217.64,4867.02 4217.36,4866.74 4217.36,4754.69 4227.53,4744.52 4227.53,4710.03 4238.41,4699.15 4238.41,4690.03 4227.53,4679.15 4227.53,4670.03 4238.41,4659.15 4238.41,4650.03 4227.53,4639.15 R57.2@4227.53,4546.06
pads on no net: U3.35

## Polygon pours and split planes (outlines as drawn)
5V_USB on Top Layer (solid, remove dead copper, pour order 6): 3797.36,4754.69 3797.36,4789.69 3812.36,4804.69 3932.36,4804.69 3967.36,4839.69 4127.36,4839.69 4127.36,4889.69 4122.36,4894.69 3832.36,4894.69 3797.36,4859.69 3752.36,4859.69 3752.36,4754.69
3.3V on Top Layer (solid, remove dead copper, pour order 8): 3702.36,4694.69 3662.36,4694.69 3662.36,4859.69 3612.36,4909.69 3612.36,5089.69 3757.36,5089.69 3757.36,4909.69 3707.36,4859.69 3707.36,4739.83 3702.36,4734.83
5V_USB on Top Layer (solid, remove dead copper, pour order 10): 4482.36,4174.69 4342.36,4174.69 4337.36,4169.69 4277.36,4169.69 4277.36,4159.69 4322.36,4159.69 4327.36,4154.69 4372.36,4154.69 4387.36,4139.69 4482.36,4139.69
$1N11929 on Bottom Layer (solid, remove dead copper, pour order 16): 4622.36,4904.69 4723.49,4904.69 4723.49,4869.69 4622.36,4869.69
$1N11847 on Bottom Layer (solid, remove dead copper, pour order 18): 4622.36,4914.69 4722.36,4914.69 4722.36,4949.69 4712.36,4959.69 4622.36,4959.69
$1N881 on Top Layer (solid, remove dead copper, pour order 0): 3937.36,4134.69 3937.36,3984.69 3972.36,3984.69 3972.36,4134.69
$1N17369 on Top Layer (solid, remove dead copper, pour order 2): 3867.36,4229.69 3877.36,4219.69 4017.36,4219.69 4032.36,4234.69 4102.36,4234.69 4102.36,4249.37 3972.69,4249.37 3972.36,4249.69 3922.36,4249.69 3917.36,4254.69 3867.36,4254.69
$1N2306 on Top Layer (solid, remove dead copper, pour order 4): 4099.75,4255.43 3951.81,4255.43 3933.45,4273.79 3933.45,4303.96 3940.18,4310.69 3940.18,4389.23 3942.74,4391.79 3973.05,4391.79 3975.18,4389.65 3975.18,4282.89 3990.42,4267.66 4099.69,4267.66 4099.75,4267.59
AGND on Bottom Layer (solid, remove dead copper, pour order 68): 4737.36,4919.69 4772.36,4919.69 4797.36,4944.69 4797.36,4964.69 4807.36,4974.69 4877.36,4974.69 4892.36,4959.69 4892.36,4754.69 4872.36,4734.69 4572.36,4734.69 4542.36,4704.69 4357.36,4704.69 4332.36,4679.69 3962.36,4679.69 3872.36,4589.69 3667.36,4589.69 3632.36,4624.69 3632.36,4679.69 3602.36,4709.69 3302.36,4709.69 3302.36,3294.69 5077.36,3294.69 5082.36,3289.69 5082.36,5054.69 5007.36,5129.69 4737.36,5129.69
AGND on Top Layer (solid, remove dead copper, pour order 12): 4742.36,4919.69 4777.36,4919.69 4802.36,4944.69 4802.36,4964.69 4812.36,4974.69 4882.36,4974.69 4897.36,4959.69 4897.36,4754.69 4877.36,4734.69 4577.36,4734.69 4547.36,4704.69 4337.36,4704.69 4312.36,4679.69 3967.36,4679.69 3877.36,4589.69 3672.36,4589.69 3637.36,4624.69 3637.36,4679.69 3607.36,4709.69 3307.36,4709.69 3307.36,3294.69 5082.36,3294.69 5087.36,3289.69 5087.36,5054.69 5012.36,5129.69 4742.36,5129.69
GND on Top Layer (solid, remove dead copper, pour order 14): 4557.36,4734.69 4536.75,4714.08 4331.75,4714.08 4302.36,4684.69 4284.76,4684.69 4279.58,4679.51 4279.58,4591.91 4257.36,4569.69 3992.36,4569.69 3977.36,4584.69 3697.36,4584.69 3637.36,4644.69 3637.36,4709.69 3627.36,4719.69 3302.36,4719.69 3302.36,5144.69 4737.36,5144.69 4737.36,4924.69 4802.36,4859.69 4802.36,4744.69 4792.36,4734.69
GND on Bottom Layer (solid, pour order 70): 4557.36,4734.69 4536.75,4714.08 4331.75,4714.08 4302.36,4684.69 4284.76,4684.69 4279.58,4679.51 4279.58,4591.91 4257.36,4569.69 3992.36,4569.69 3977.36,4584.69 3697.36,4584.69 3637.36,4644.69 3637.36,4709.69 3627.36,4719.69 3302.36,4719.69 3302.36,5144.69 4737.36,5144.69 4737.36,4924.69 4802.36,4859.69 4802.36,4744.69 4792.36,4734.69
$1N2534 on Bottom Layer (solid, pour order 72): 3868.52,3557.85 3870.26,3559.59 3870.26,3590.71 3867.18,3593.79 3781.9,3593.79 3779.95,3591.85
$1N2549 on Bottom Layer (solid, pour order 74): 3777.36,3539.69 3867.36,3539.69 3872.36,3534.69 3872.36,3504.69 3867.36,3499.69 3782.36,3499.69
$1N3593 on Bottom Layer (solid, pour order 20): 3622.36,3664.69 3692.36,3664.69 3692.36,3564.69 3622.36,3564.69
$1N2541 on Bottom Layer (solid, pour order 22): 3707.36,3784.69 3752.36,3784.69 3752.36,3684.69 3707.36,3684.69
$1N3616 on Bottom Layer (solid, pour order 24): 3937.36,3729.69 3992.36,3729.69 3992.36,3609.69 3937.36,3609.69
$1N2549 on Bottom Layer (solid, pour order 26): 4002.36,3839.69 4042.36,3839.69 4042.36,3754.69 4002.36,3754.69
$1N2534 on Bottom Layer (solid, pour order 28): 3947.36,3839.69 3987.36,3839.69 3987.36,3754.69 3947.36,3754.69
$1N3155 on Bottom Layer (solid, pour order 30): 4372.36,3859.69 4412.36,3859.69 4412.36,3764.69 4372.36,3764.69
$1N3148 on Bottom Layer (solid, pour order 32): 4422.36,3859.69 4462.36,3859.69 4462.36,3764.69 4422.36,3764.69
$1N17152 on Bottom Layer (solid, pour order 34): 4692.36,3674.69 4772.36,3674.69 4772.36,3549.69 4692.36,3549.69
$1N2515 on Bottom Layer (solid, pour order 36): 3772.36,4049.69 3862.36,4049.69 3862.36,4009.69 3772.36,4009.69
$1N2508 on Bottom Layer (solid, pour order 38): 3772.36,4099.69 3857.36,4099.69 3857.36,4064.69 3772.36,4064.69
$1N2502 on Bottom Layer (solid, pour order 40): 3777.36,4529.69 3867.36,4529.69 3867.36,4489.69 3777.36,4489.69
$1N2496 on Bottom Layer (solid, pour order 42): 3777.36,4579.69 3872.36,4579.69 3872.36,4544.69 3777.36,4544.69
$1N3547 on Bottom Layer (solid, pour order 44): 3632.36,4589.69 3752.36,4589.69 3752.36,4539.69 3632.36,4539.69
$1N16896 on Bottom Layer (solid, pour order 46): 4637.36,4594.69 4757.36,4594.69 4757.36,4544.69 4637.36,4544.69
$1N3102 on Bottom Layer (solid, pour order 48): 4522.36,4589.69 4612.36,4589.69 4612.36,4549.69 4522.36,4549.69
$1N3111 on Bottom Layer (solid, pour order 50): 4522.36,4534.69 4612.36,4534.69 4612.36,4494.69 4522.36,4494.69
$1N17239 on Bottom Layer (solid, pour order 52): 4517.36,4054.69 4612.36,4054.69 4612.36,4014.69 4517.36,4014.69
$1N17244 on Bottom Layer (solid, pour order 54): 4517.36,4109.69 4612.36,4109.69 4612.36,4070.1 4517.36,4070.1
$1N3136 on Bottom Layer (solid, pour order 56): 4692.36,3789.69 4732.36,3789.69 4732.36,3699.69 4692.36,3699.69
$1N3142 on Bottom Layer (solid, pour order 58): 4637.36,3789.69 4677.36,3789.69 4677.36,3699.69 4637.36,3699.69
$1N3571 on Bottom Layer (solid, pour order 60): 3617.36,4109.69 3747.36,4109.69 3747.36,4054.69 3617.36,4054.69
$1N16947 on Bottom Layer (solid, pour order 62): 4637.36,4114.69 4757.36,4114.69 4757.36,4064.69 4637.36,4064.69
$1N2525 on Bottom Layer (solid, pour order 64): 3647.36,3779.69 3687.36,3779.69 3687.36,3689.69 3647.36,3689.69
$1N20017 on Bottom Layer (solid, pour order 66): 4417.36,3744.69 4467.36,3744.69 4467.36,3619.69 4417.36,3619.69

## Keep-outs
Board Outline Layer:
  the board outline again, w10

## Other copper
Top Layer:
  region net 5V_USB: 4374.5,4158.15 4374.5,4168.15 ccw(c4374.5,4194.2) 4389.5,4172.9 4389.5,4150.65 ccw(c4374.5,4139.4)
  region net $1N881: 3970.7,4139.17 3975.8,4130.13 ccw(c3997.02,4114.22) 3970.5,4114.22 3954.79,4133.87 ccw(c3954.79,4160.38)
  region net GND: 4393.46,4236.16 4386.39,4243.23 ccw(c4358.52,4257.09) 4389.64,4257.09 4409.29,4241.38 ccw(c4409.29,4214.79)
  region net GND: 4440.08,4262.13 4440.08,4252.13 ccw(c4440.08,4233.38) 4425.08,4244.63 4425.08,4269.63 ccw(c4440.08,4280.88)
  region net 3.3V: 4379.92,4307.25 4379.92,4317.25 ccw(c4379.92,4327.3) 4389.64,4324.75 4389.64,4299.75 ccw(c4379.92,4297.2)
  region net 3.3V: 3689.8,4681.97 3679.8,4681.97 ccw(c3661.05,4681.97) 3672.3,4696.97 3697.3,4696.97 ccw(c3708.55,4681.97)
  region net $1N2306: 3970.97,4279.92 3968.17,4268.59 ccw(c3952.26,4247.37) 3952.26,4273.89 3964.99,4295.15 ccw(c3987.35,4295.15)
  region net 3.3V: 4794.16,4909.73 4800.48,4921.73 4802.06,4921.89 4803.67,4922.35 4805.29,4923.07 4806.92,4924.03 4810.19,4926.48 4813.44,4929.43 4819.69,4935.73 4822.59,4938.51 4825.29,4940.69 4818.97,4887.92 4815.7,4891.99 4813.04,4895.93 4810.69,4899.61 4808.4,4902.91 4807.18,4904.38 4805.87,4905.7 4804.43,4906.87 4802.84,4907.86 4801.05,4908.65 4799.03,4909.24 4796.74,4909.61
  region net $1N12022: 3949.96,4776.01 3949.96,4786.01 ccw(c3949.96,4804.76) 3964.96,4793.51 3964.96,4768.51 ccw(c3949.96,4757.26)
  region net $1N1310: 4012.66,4347.34 4002.66,4347.34 ccw(c3983.91,4347.34) 3995.16,4362.34 4020.16,4362.34 ccw(c4031.41,4347.34)
  region net DAISY: 4002.66,4468.41 4012.66,4468.41 ccw(c4031.41,4468.41) 4020.16,4453.41 3995.16,4453.41 ccw(c3983.91,4468.41)
  region net 3.3V: 3978.64,4524.46 3972.7,4532.66 ccw(c3951.49,4548.57) 3978,4548.57 3994.55,4529.76 ccw(c3994.55,4503.24)
  region net 3.3V: 3972.7,4560.88 3979.49,4568.23 ccw(c3994.55,4591.47) 3994.55,4563.78 3978,4544.97 ccw(c3951.49,4544.97)
  region net RST: 4048.2,4578.78 4058.2,4578.78 ccw(c4076.95,4578.78) 4065.7,4563.78 4040.7,4563.78 ccw(c4029.45,4578.78)
  region net RST: 4058.2,4514.76 4048.2,4514.76 ccw(c4029.45,4514.76) 4040.7,4529.76 4065.7,4529.76 ccw(c4076.95,4514.76)
  region net $1N12022: 3951.85,4786.01 3951.85,4776.01 ccw(c3951.85,4721.78) 3936.85,4773.9 3936.85,4793.51 ccw(c3951.85,4804.76)
  region net SPI1_MOSI: 4119.2,4576.94 4129.2,4576.94 ccw(c4147.95,4576.94) 4136.7,4561.94 4111.7,4561.94 ccw(c4100.45,4576.94)
  region net SDI: 4129.2,4455.87 4119.2,4455.87 ccw(c4100.45,4455.87) 4111.7,4470.87 4136.7,4470.87 ccw(c4147.95,4455.87)
  region net SPI1_MISO: 4171.5,4576.94 4181.5,4576.94 ccw(c4200.25,4576.94) 4189,4561.94 4164,4561.94 ccw(c4152.75,4576.94)
  region net SDO: 4181.5,4455.87 4171.5,4455.87 ccw(c4152.75,4455.87) 4164,4470.87 4189,4470.87 ccw(c4200.25,4455.87)
  region net SPI1_SCK: 4222.53,4576.94 4232.53,4576.94 ccw(c4251.28,4576.94) 4240.03,4561.94 4215.03,4561.94 ccw(c4203.78,4576.94)
  region net SCLK: 4232.53,4465.53 4222.53,4465.53 ccw(c4215.03,4462.93) 4215.03,4470.87 4240.03,4470.87 ccw(c4240.03,4462.93)
  region net SPI1_CS: 4274.58,4576.87 4284.58,4576.87 ccw(c4303.33,4576.87) 4292.08,4561.87 4267.08,4561.87 ccw(c4255.83,4576.87)
  region net CS: 4284.58,4466.29 4274.58,4466.29 ccw(c4267.08,4462.3) 4267.08,4470.8 4292.08,4470.8 ccw(c4292.08,4462.3)
  region net $1N17369: 3852.89,4279.99 3842.89,4279.99 3842.72,4281.73 3842.22,4283.63 3841.47,4285.43 3840.51,4286.88 3855.27,4286.88 3854.32,4285.43 3853.56,4283.63 3853.07,4281.73
  region net SDI: 4113.36,4325.69 4113.36,4315.69 ccw(c4113.36,4211.65) 4099.66,4314.78 4099.66,4326.59 ccw(c4113.36,4429.72)
  region net AGND: 4109.89,4227.17 4109.89,4217.17 ccw(c4109.89,4157.84) 4099.56,4216.26 4099.56,4228.07 ccw(c4109.89,4286.5)
  region net $1N2515: 4114.56,4050 4114.56,4040 ccw(c4114.56,3915.23) 4099.56,4039.09 4099.56,4050.9 ccw(c4114.56,4174.76)
  region net 5V_USB: 4261.76,4158.15 4261.76,4168.15 ccw(c4261.76,4292.91) 4276.76,4169.05 4276.76,4157.24 ccw(c4261.76,4033.38)
  region net 5V_USB: 4342.94,4168.15 4342.94,4158.15 ccw(c4342.94,4033.38) 4327.94,4157.24 4327.94,4169.05 ccw(c4342.94,4292.91)
  region net 3.3V: 4264.56,4236.89 4264.56,4246.89 ccw(c4264.56,4329.66) 4276.76,4247.79 4276.76,4235.98 ccw(c4264.56,4154.11)
  region net 5V_USB: 3868.03,4191.2 3885.98,4187.4 ccw(c3908.06,4209.48) 3899.3,4179.5 3877.55,4179.5 ccw(c3815.9,4139.07)
  region net $1N17369: 3862.55,4237.49 3862.55,4247.49 ccw(c3862.55,4267.42) 3877.55,4254.3 3877.55,4230.68 ccw(c3862.55,4217.57)
  region net 3.3V: 3691.14,4982.54 3679.14,4982.54 ccw(c3656.64,4982.54) 3670.14,5000.54 3700.14,5000.54 ccw(c3713.64,4982.54)
  region net $1N2496: 4029.18,4124.94 4022.11,4117.87 4021.24,4118.61 4020.26,4119.23 4018.05,4120.16 4015.68,4120.72 4013.33,4120.98 4026.07,4133.72 4026.33,4131.37 4026.89,4129 4027.82,4126.79 4028.44,4125.81
  region net $1N11929: 4176.35,4256.98 4177.17,4266.98 4178.31,4267.06 4179.44,4267.31 4181.63,4268.17 4183.69,4269.39 4185.58,4270.79 4184.76,4252.8 4182.96,4254.33 4180.87,4255.67 4178.63,4256.62 4177.49,4256.88
  region net $1N2534: 3975.1,3902.21 3985.1,3902.21 3985.19,3901.07 3985.45,3899.93 3986.36,3897.72 3987.64,3895.65 3989.11,3893.8 3971.1,3893.8 3972.57,3895.65 3973.85,3897.72 3974.76,3899.93 3975.01,3901.07
  region net $1N2549: 4022.36,3881.04 4032.36,3881.04 4032.45,3879.9 4032.71,3878.77 4033.61,3876.55 4034.9,3874.48 4036.37,3872.63 4018.36,3872.63 4019.83,3874.48 4021.11,3876.55 4022.02,3878.77 4022.27,3879.9
  region net $1N3155: 4345.41,3939.67 4355.41,3939.67 4355.5,3938.54 4355.76,3937.4 4356.66,3935.19 4357.95,3933.11 4359.42,3931.27 4341.41,3931.27 4342.88,3933.11 4344.16,3935.19 4345.07,3937.4 4345.32,3938.54
  region net $1N3148: 4438.53,3902.42 4448.53,3902.42 4448.62,3901.28 4448.88,3900.15 4449.79,3897.94 4451.07,3895.86 4452.54,3894.02 4434.53,3894.02 4436,3895.86 4437.28,3897.94 4438.19,3900.15 4438.44,3901.28
  region net $1N3142: 4607.64,3798.91 4614.71,3805.98 4615.58,3805.24 4616.56,3804.62 4618.77,3803.69 4621.14,3803.13 4623.49,3802.87 4610.75,3790.13 4610.49,3792.48 4609.93,3794.85 4609,3797.06 4608.38,3798.04
  region net $1N3136: 4669.15,3805.65 4669.15,3815.65 4670.29,3815.74 4671.42,3816 4673.64,3816.9 4675.71,3818.19 4677.56,3819.66 4677.56,3801.65 4675.71,3803.12 4673.64,3804.4 4671.42,3805.31 4670.29,3805.56
  region net $1N17239: 4466.3,4040.09 4473.79,4050.09 4475.85,4050.21 4478.03,4050.55 4482.19,4051.59 4474.71,4035.2 4474.11,4036.23 4473.3,4037.17 4472.31,4038 4471.2,4038.71 4470,4039.29 4468.75,4039.72 4467.51,4039.99
  region net $1N2515: 4098.06,4040 4097.97,4050 4099.1,4050.09 4100.24,4050.34 4102.46,4051.25 4104.53,4052.54 4106.37,4054.02 4106.46,4036.01 4104.61,4037.47 4102.54,4038.75 4100.33,4039.65 4099.19,4039.91
  region net $1N2525: 3893.71,3939.69 3893.71,3929.69 3892.57,3929.6 3891.44,3929.35 3889.22,3928.44 3887.15,3927.16 3885.3,3925.69 3885.3,3943.7 3887.15,3942.23 3889.22,3940.94 3891.44,3940.04 3892.57,3939.78
  region net $1N2541: 3905.39,3889.79 3912.46,3882.72 3911.72,3881.85 3911.09,3880.87 3910.17,3878.66 3909.61,3876.28 3909.35,3873.94 3896.61,3886.68 3898.95,3886.94 3901.33,3887.5 3903.54,3888.42 3904.52,3889.05
  region net $1N3111: 4399.34,4099.6 4392.27,4106.67 4393.01,4107.53 4393.63,4108.52 4394.55,4110.72 4395.11,4113.1 4395.38,4115.44 4408.11,4102.71 4405.77,4102.44 4403.39,4101.88 4401.19,4100.96 4400.2,4100.34
  region net 5V_USB: 4272.51,4168.15 4262.52,4158.15 4258.3,4158.15 4256.27,4158.05 4254.11,4157.81 4264.1,4172.21 4264.54,4170.97 4265.22,4170.02 4266.12,4169.3 4267.19,4168.79 4268.4,4168.46 4269.72,4168.26
  region net 3.3V: 4276.93,4246.89 4280.22,4236.89 4279.1,4236.78 4277.93,4236.49 4275.6,4235.45 4273.48,4233.98 4271.82,4232.29 4268.52,4250 4270.51,4248.85 4272.57,4247.86 4274.7,4247.15
  region net 5V_USB: 3793.61,4321.34 3783.61,4321.34 3783.52,4322.48 3783.27,4323.62 3782.36,4325.83 3781.08,4327.9 3779.61,4329.75 3797.62,4329.75 3796.15,4327.9 3794.86,4325.83 3793.96,4323.62 3793.7,4322.48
